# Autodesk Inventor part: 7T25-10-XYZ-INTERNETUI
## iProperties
Created: 2010-11
Part Number: 7T25-10-XYZ-INTERNETUI
Document SubType Name: Modeling
Designer: Darius
Author: Darius
Translation Standard: STEP AP203
File Name: 7T25-10-XYZ.STEP
Preprocessor: SolidWorks 2003240
Postprocessor: Build: 272, Release: 10 SP3a - Date: Thu 12/15/2005
Sent Units: MILLIMETERS
Uncertainty: 1e-05
